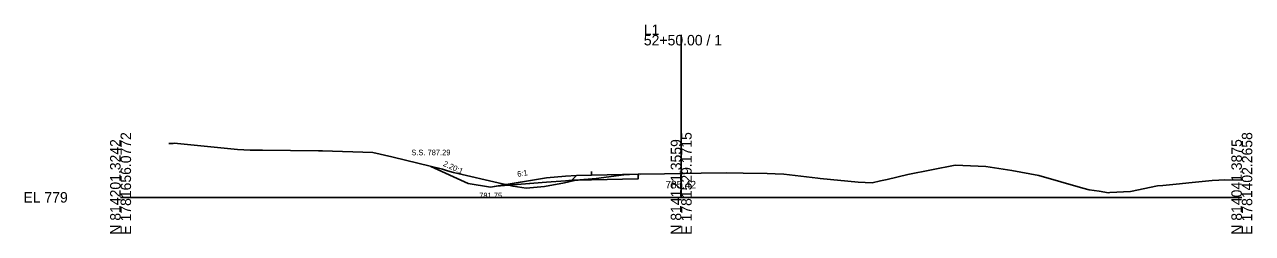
# Model space of a CAD drawing. Extents: x 5574 to 10203, y -10 to 9546.
# Drawn here: x 5574.3 to 5902.8, y 9490.3 to 9546.4 of the extents above; entities that cross this region are included whole.
import ezdxf

# ---------------------------------------------------------------- set-up
doc = ezdxf.new("R2010")
doc.units = 0
for name, color, linetype in [('Exist Cross Section Cell', 7, 'Continuous'), ('Exist XS Center Line Elevation Label', 7, 'Continuous'), ('Exist XS Ground Line', 7, 'Continuous'), ('Prop XS Ditch Slope Text', 7, 'Continuous'), ('Prop XS Ditch Standard Text', 7, 'Continuous'), ('Prop XS Dump Level', 7, 'Continuous'), ('Prop XS Earthwork Shape', 7, 'Continuous'), ('Prop XS EOT Tick Mark', 7, 'Continuous'), ('Prop XS Finish Grade', 7, 'Continuous'), ('Prop XS Finish Grade Earthwork', 7, 'Continuous'), ('Prop XS Finish Grade Paved Shoulder', 7, 'Continuous'), ('Prop XS Finish Grade Pavement', 7, 'Continuous'), ('Prop XS Hydro Typical Ditch Data', 7, 'Continuous'), ('Prop XS Pvmt Edge Slope', 7, 'Continuous'), ('Prop XS Side Slope Text', 7, 'Continuous'), ('Prop XS SS Elevation Text', 7, 'Continuous'), ('Prop XS Subgrade Earthwork', 7, 'Continuous'), ('Scratch_Level_3', 7, 'Continuous'), ('Scratch_Level_6', 7, 'Continuous')]:
    doc.layers.add(name, color=color, linetype=linetype)

msp = doc.modelspace()

# ---------------------------------------------------------------- linework, layer by layer
at = {"layer": 'Exist Cross Section Cell'}
for p, q in [((5750, 9500), (5750, 9543.56)), ((5600, 9500), (5750, 9500)), ((5750, 9500), (5900, 9500))]:
    msp.add_line(p, q, dxfattribs=at)
at = {"layer": 'Exist XS Ground Line'}
for p, q in [((5612.88, 9514.44), (5613.54, 9514.42)), ((5613.54, 9514.42), (5614.06, 9514.47)), ((5614.06, 9514.47), (5614.51, 9514.52)), ((5614.51, 9514.52), (5615.22, 9514.45)), ((5615.22, 9514.45), (5631.32, 9512.87)), ((5631.32, 9512.87), (5634.7, 9512.63)), ((5634.7, 9512.63), (5638, 9512.62)), ((5638, 9512.62), (5652.98, 9512.5)), ((5652.98, 9512.5), (5653.45, 9512.51)), ((5653.45, 9512.51), (5654.05, 9512.48)), ((5654.05, 9512.48), (5667.5, 9512)), ((5667.5, 9512), (5672.6, 9510.85)), ((5672.6, 9510.85), (5672.91, 9510.79)), ((5672.91, 9510.79), (5686.11, 9507.53)), ((5810.64, 9506.09), (5823.31, 9508.6)), ((5823.31, 9508.6), (5831.53, 9508.27)), ((5831.53, 9508.27), (5838.45, 9507.23)), ((5686.11, 9507.53), (5687.45, 9507.15)), ((5687.45, 9507.15), (5689.07, 9506.71)), ((5689.07, 9506.71), (5702.18, 9503.65)), ((5718.75, 9503.88), (5721.46, 9504.53)), ((5721.46, 9504.53), (5727.27, 9505.03)), ((5727.27, 9505.03), (5734.63, 9506.01)), ((5734.63, 9506.01), (5736.13, 9506.09)), ((5736.13, 9506.09), (5738.51, 9506.22)), ((5738.51, 9506.22), (5745.57, 9506.35)), ((5745.57, 9506.35), (5750, 9506.42)), ((5750, 9506.42), (5750.6, 9506.43)), ((5750.6, 9506.43), (5755.34, 9506.49)), ((5755.34, 9506.49), (5762.02, 9506.57)), ((5762.02, 9506.57), (5766.6, 9506.51)), ((5766.6, 9506.51), (5772.96, 9506.43)), ((5772.96, 9506.43), (5775.17, 9506.32)), ((5775.17, 9506.32), (5777.48, 9506.22)), ((5777.48, 9506.22), (5786.52, 9505.14)), ((5786.52, 9505.14), (5787.16, 9505.09)), ((5787.16, 9505.09), (5797.38, 9504.07)), ((5803.36, 9504.4), (5805.07, 9504.75)), ((5805.07, 9504.75), (5810.64, 9506.09)), ((5838.45, 9507.23), (5845.67, 9505.85)), ((5845.67, 9505.85), (5857.49, 9502.51)), ((5885.82, 9503.9), (5892.05, 9504.51)), ((5892.05, 9504.51), (5893.83, 9504.6)), ((5893.83, 9504.6), (5895.35, 9504.66)), ((5895.35, 9504.66), (5900, 9504.62)), ((5702.18, 9503.65), (5705.02, 9502.98)), ((5705.02, 9502.98), (5708.55, 9502.49)), ((5708.55, 9502.49), (5713.41, 9502.89)), ((5713.41, 9502.89), (5718.75, 9503.88)), ((5797.38, 9504.07), (5801.05, 9503.92)), ((5801.05, 9503.92), (5803.36, 9504.4)), ((5857.49, 9502.51), (5859.17, 9502.04)), ((5859.17, 9502.04), (5861.84, 9501.63)), ((5861.84, 9501.63), (5864.3, 9501.25)), ((5864.3, 9501.25), (5864.69, 9501.26)), ((5864.69, 9501.26), (5870.21, 9501.57)), ((5870.21, 9501.57), (5877.44, 9503.1)), ((5877.44, 9503.1), (5878.86, 9503.17)), ((5878.86, 9503.17), (5883.29, 9503.61)), ((5883.29, 9503.61), (5885.82, 9503.9))]:
    msp.add_line(p, q, dxfattribs=at)
at = {"layer": 'Prop XS Dump Level'}
msp.add_line((5738.5, 9506.19), (5726, 9505.94), dxfattribs=at)
msp.add_line((5738.5, 9506.19), (5726, 9505.94), dxfattribs=at)
at = {"layer": 'Prop XS Earthwork Shape'}
for points in [[(5693, 9503.75), (5683, 9508.29), (5686.11, 9507.53), (5687.45, 9507.15), (5689.07, 9506.71), (5702.18, 9503.65), (5703.82, 9503.26), (5700.46, 9502.99), (5699, 9502.75)], [(5722, 9504.64), (5720.72, 9504.61), (5719, 9504.47), (5714, 9504.07), (5703.82, 9503.26), (5705.02, 9502.98), (5708.55, 9502.49), (5713.41, 9502.89), (5718.75, 9503.88), (5721.46, 9504.53), (5722.89, 9504.66)], [(5722.89, 9504.66), (5727.27, 9505.03), (5734.63, 9506.01), (5736.13, 9506.09), (5738.49, 9506.22), (5738.49, 9504.97), (5726, 9504.72)]]:
    msp.add_lwpolyline(points, close=True, dxfattribs=at)
at = {"layer": 'Prop XS EOT Tick Mark'}
msp.add_line((5726, 9505.97), (5726, 9506.97), dxfattribs=at)
at = {"layer": 'Prop XS Finish Grade'}
for p, q in [((5714, 9505.25), (5700.46, 9502.99)), ((5719, 9505.65), (5714, 9505.25)), ((5722, 9505.89), (5719, 9505.65))]:
    msp.add_line(p, q, dxfattribs=at)
at = {"layer": 'Prop XS Finish Grade Earthwork'}
for p, q in [((5693, 9503.75), (5683, 9508.29)), ((5699, 9502.75), (5693, 9503.75)), ((5700.46, 9502.99), (5699, 9502.75))]:
    msp.add_line(p, q, dxfattribs=at)
at = {"layer": 'Prop XS Finish Grade Paved Shoulder'}
msp.add_line((5726, 9505.97), (5722, 9505.89), dxfattribs=at)
at = {"layer": 'Prop XS Finish Grade Pavement'}
msp.add_line((5738.49, 9506.22), (5726, 9505.97), dxfattribs=at)
at = {"layer": 'Prop XS Hydro Typical Ditch Data'}
for p, q in [((5693, 9503.75), (5683, 9508.29)), ((5714, 9505.25), (5699, 9502.75)), ((5699, 9502.75), (5693, 9503.75))]:
    msp.add_line(p, q, dxfattribs=at)
at = {"layer": 'Prop XS Pvmt Edge Slope'}
msp.add_line((5722, 9505.89), (5720.72, 9504.61), dxfattribs=at)
at = {"layer": 'Prop XS Subgrade Earthwork'}
for p, q in [((5719, 9504.47), (5714, 9504.07)), ((5720.72, 9504.61), (5719, 9504.47)), ((5722, 9504.64), (5720.72, 9504.61)), ((5726, 9504.72), (5722, 9504.64)), ((5738.49, 9504.97), (5726, 9504.72)), ((5738.49, 9504.97), (5738.49, 9506.22)), ((5714, 9504.07), (5700.46, 9502.99))]:
    msp.add_line(p, q, dxfattribs=at)
at = {"layer": 'Scratch_Level_3'}
for p, q in [((5714, 9505.25), (5700.46, 9502.99)), ((5719, 9505.65), (5714, 9505.25)), ((5714, 9504.07), (5719, 9504.47)), ((5722, 9505.89), (5719, 9505.65)), ((5719, 9504.47), (5720.72, 9504.61)), ((5720.72, 9504.61), (5722, 9505.89)), ((5700.46, 9502.99), (5714, 9504.07))]:
    msp.add_line(p, q, dxfattribs=at)
at = {"layer": 'Scratch_Level_6'}
for points in [[(5722.89, 9504.66), (5727.27, 9505.03), (5734.63, 9506.01), (5736.13, 9506.09), (5738.49, 9506.22), (5738.49, 9504.97), (5726, 9504.72)], [(5703.1, 9503.43), (5700.46, 9502.99), (5703.82, 9503.26)]]:
    msp.add_lwpolyline(points, close=True, dxfattribs=at)

# ---------------------------------------------------------------- texts
at = {"layer": 'Exist Cross Section Cell'}
for s, p in [('L1', (5740, 9543.56)), ('52+50.00 / 1', (5740, 9540.76)), ('EL 779', (5574, 9498.6))]:
    msp.add_text(s, height=2.8, dxfattribs=at).set_placement(p)
for s, p in [('N 814201.3242', (5600, 9490)), ('E 1781656.0772', (5602.8, 9490)), ('N 814121.3559', (5750, 9490)), ('E 1781529.1715', (5752.8, 9490)), ('N 814041.3875', (5900, 9490)), ('E 1781402.2658', (5902.8, 9490))]:
    msp.add_text(s, height=2.8, rotation=90, dxfattribs=at).set_placement(p)
at = {"layer": 'Exist XS Center Line Elevation Label'}
msp.add_text('785.42', height=2, dxfattribs=at).set_placement((5745.79, 9502.42))
at = {"layer": 'Prop XS Ditch Slope Text'}
msp.add_text('6:1', height=1.5, rotation=9.4623, dxfattribs=at).set_placement((5706.25, 9505.48))
at = {"layer": 'Prop XS Ditch Standard Text'}
msp.add_text('781.75', height=1.5, dxfattribs=at).set_placement((5695.95, 9499.75))
at = {"layer": 'Prop XS Dump Level'}
for s, height, p in [('Case4', 0.04, (5714, 9505.21)), ('Eop', 0.3, (5738.49, 9505.92))]:
    msp.add_text(s, height=height, dxfattribs=at).set_placement(p)
at = {"layer": 'Prop XS Side Slope Text'}
msp.add_text('2.20:1', height=1.5, rotation=335.5533, dxfattribs=at).set_placement((5686.17, 9508.5))
at = {"layer": 'Prop XS SS Elevation Text'}
msp.add_text('S.S. 787.29', height=1.5, dxfattribs=at).set_placement((5677.78, 9511.29))

doc.saveas('drawing.dxf')
